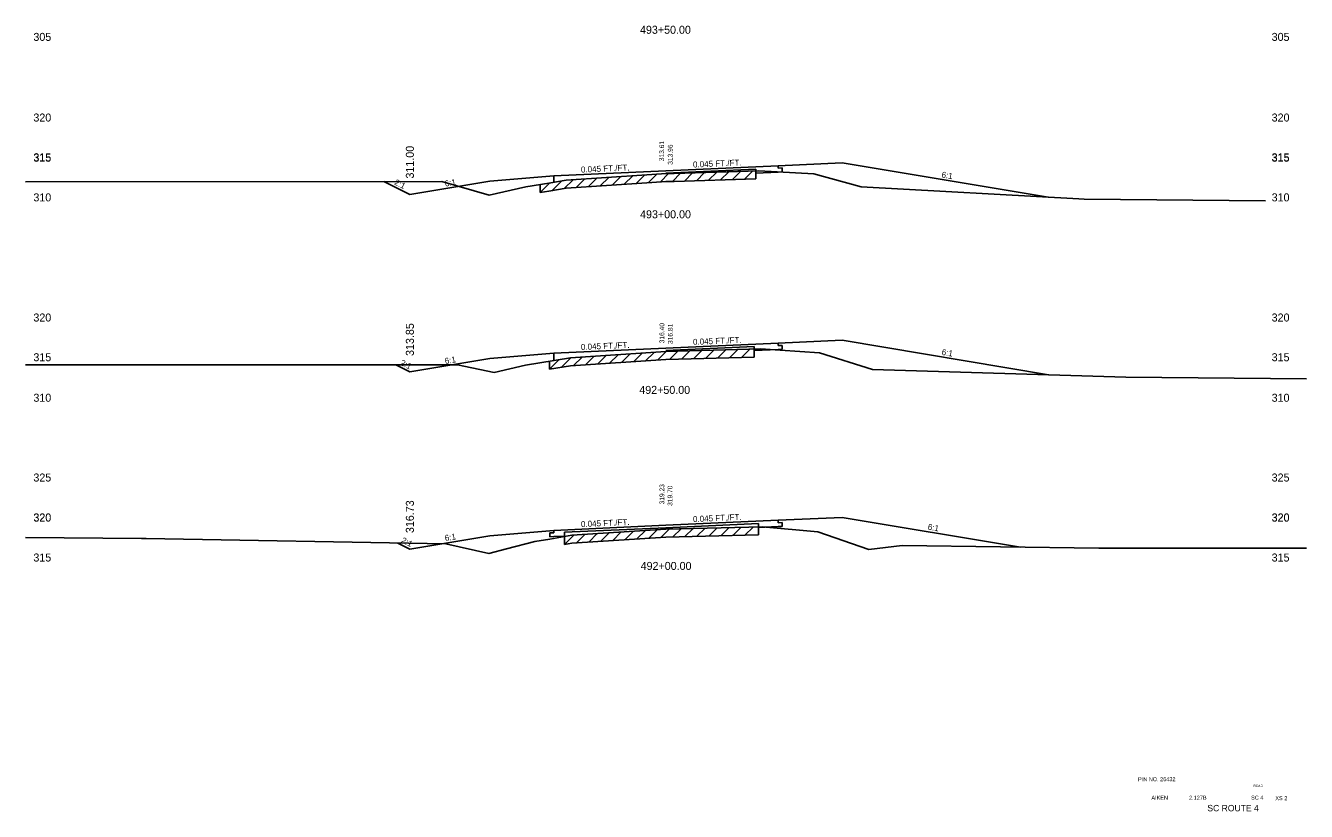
# Model space of a CAD drawing. Extents: x 883 to 1160, y 1002 to 4323.
# Drawn here: x 1000 to 1160, y 1214 to 1312.1 of the extents above; entities that cross this region are included whole.
import ezdxf

# ---------------------------------------------------------------- set-up
doc = ezdxf.new("R2010")
doc.units = 0
for name, color, linetype in [('Level 1', 7, 'Continuous'), ('Level 10', 7, 'Continuous'), ('Level 11', 7, 'Continuous'), ('Level 12', 7, 'Continuous'), ('Level 3', 7, 'Continuous'), ('Level 32', 7, 'Continuous'), ('Level 33', 7, 'Continuous'), ('Level 53', 7, 'Continuous'), ('Level 59', 7, 'Continuous'), ('Level 6', 7, 'Continuous'), ('Level 60', 7, 'Continuous'), ('Level 61', 7, 'Continuous'), ('Level 7', 7, 'Continuous')]:
    doc.layers.add(name, color=color, linetype=linetype)

msp = doc.modelspace()

# ---------------------------------------------------------------- linework, layer by layer
at = {"layer": 'Level 11'}
for p, q in [((1094, 1294.29), (1094, 1294.59)), ((1066, 1292.55), (1066, 1293.33)), ((1094.5, 1294.32), (1094, 1294.29)), ((1094, 1293.81), (1094.5, 1293.84)), ((1094.5, 1293.84), (1094.5, 1294.32)), ((1094, 1272.14), (1094, 1272.44)), ((1094.5, 1272.16), (1094, 1272.14)), ((1094.5, 1271.68), (1094.5, 1272.16)), ((1066, 1270.27), (1066, 1271.18)), ((1094, 1271.66), (1094.5, 1271.68)), ((1094, 1250.03), (1094, 1250.33)), ((1094.5, 1250.05), (1094, 1250.03)), ((1094.5, 1249.57), (1094.5, 1250.05)), ((1066, 1248.77), (1065.5, 1248.75)), ((1065.5, 1248.75), (1065.5, 1248.27)), ((1065.5, 1248.27), (1066, 1248.29)), ((1066, 1249.07), (1066, 1248.77)), ((1094, 1249.55), (1094.5, 1249.57))]:
    msp.add_line(p, q, dxfattribs=at)
at = {"layer": 'Level 12'}
for p, q in [((1091.21, 1293.96), (1091.21, 1293.69)), ((1091.21, 1293.69), (1094, 1293.81)), ((1091, 1271.7), (1091, 1271.53)), ((1091, 1271.53), (1094, 1271.66)), ((1067.34, 1248.35), (1066, 1248.29)), ((1067.34, 1248.32), (1067.34, 1248.35)), ((1091.56, 1249.44), (1094, 1249.55)), ((1091.56, 1249.51), (1091.56, 1249.44))]:
    msp.add_line(p, q, dxfattribs=at)
at = {"layer": 'Level 53'}
for p, q in [((1080, 1293.66), (1091.21, 1294.17)), ((1091.21, 1294.17), (1091.21, 1293.96)), ((1080, 1271.51), (1091, 1272.01)), ((1091, 1272.01), (1091, 1271.7)), ((1080, 1249.4), (1091.56, 1249.92)), ((1091.56, 1249.92), (1091.56, 1249.51)), ((1080, 1249.4), (1067.34, 1248.83)), ((1067.34, 1248.83), (1067.34, 1248.32))]:
    msp.add_line(p, q, dxfattribs=at)
at = {"layer": 'Level 59'}
for p, q in [((1080, 1293.96), (1094, 1294.59)), ((1066, 1293.33), (1080, 1293.96)), ((1080, 1271.81), (1094, 1272.44)), ((1066, 1271.18), (1080, 1271.81)), ((1066, 1249.07), (1080, 1249.7)), ((1080, 1249.7), (1094, 1250.33))]:
    msp.add_line(p, q, dxfattribs=at)
at = {"layer": 'Level 6'}
for p, q in [((1094, 1294.59), (1102, 1294.95)), ((1058, 1292.67), (1066, 1293.33)), ((1094, 1272.44), (1102, 1272.8)), ((1058, 1270.52), (1066, 1271.18)), ((1094, 1250.33), (1102, 1250.69)), ((1058, 1248.4), (1066, 1249.07))]:
    msp.add_line(p, q, dxfattribs=at)
at = {"layer": 'Level 60'}
for p, q in [((1067.54, 1292.8), (1077.61, 1293.47)), ((1077.61, 1293.47), (1079.44, 1293.6)), ((1079.44, 1293.6), (1080, 1293.62)), ((1080, 1293.62), (1081, 1293.65)), ((1081, 1293.65), (1091.58, 1293.98)), ((1091.58, 1293.98), (1098.48, 1293.59)), ((1098.48, 1293.59), (1104.37, 1291.95)), ((1000, 1292.61), (1052, 1292.63)), ((1052, 1292.63), (1057.92, 1290.94)), ((1057.92, 1290.94), (1062.51, 1291.98)), ((1062.51, 1291.98), (1065.37, 1292.44)), ((1065.37, 1292.44), (1067.54, 1292.8)), ((1104.37, 1291.95), (1131.56, 1290.45)), ((1131.56, 1290.45), (1132.26, 1290.43)), ((1132.26, 1290.43), (1154.9, 1290.2)), ((1064.22, 1269.98), (1068.06, 1270.61)), ((1068.06, 1270.61), (1080, 1271.4)), ((1080, 1271.4), (1091.82, 1271.72)), ((1091.82, 1271.72), (1099.16, 1271.23)), ((1099.16, 1271.23), (1105.81, 1269.17)), ((1000, 1269.76), (1050.87, 1269.72)), ((1050.87, 1269.72), (1053.96, 1269.72)), ((1053.96, 1269.72), (1058.54, 1268.8)), ((1058.54, 1268.8), (1062.44, 1269.68)), ((1062.44, 1269.68), (1064.22, 1269.98)), ((1105.81, 1269.17), (1137.43, 1268.22)), ((1137.43, 1268.22), (1160, 1268)), ((1000, 1248.2), (1014.49, 1248.05)), ((1014.49, 1248.05), (1015.07, 1248.05)), ((1015.07, 1248.05), (1052.49, 1247.39)), ((1065.49, 1247.99), (1068.24, 1248.48)), ((1068.24, 1248.48), (1080, 1249.23)), ((1080, 1249.23), (1092.05, 1249.52)), ((1092.05, 1249.52), (1098.96, 1248.9)), ((1098.96, 1248.9), (1105.34, 1246.69)), ((1052.49, 1247.39), (1057.87, 1246.2)), ((1057.87, 1246.2), (1060.09, 1246.76)), ((1060.09, 1246.76), (1063.63, 1247.66)), ((1063.63, 1247.66), (1065.49, 1247.99)), ((1105.34, 1246.69), (1109.5, 1247.17)), ((1109.5, 1247.17), (1134.07, 1246.84)), ((1134.07, 1246.84), (1140.73, 1246.84)), ((1140.73, 1246.84), (1160, 1246.83))]:
    msp.add_line(p, q, dxfattribs=at)
at = {"layer": 'Level 61'}
for p, q in [((1068.39, 1292.85), (1067.29, 1291.76)), ((1069.87, 1292.95), (1068.79, 1291.88)), ((1071.37, 1293.05), (1070.29, 1291.98)), ((1072.87, 1293.15), (1071.79, 1292.08)), ((1074.37, 1293.26), (1073.29, 1292.18)), ((1075.87, 1293.36), (1074.79, 1292.28)), ((1077.37, 1293.46), (1076.29, 1292.39)), ((1078.87, 1293.56), (1077.8, 1292.49)), ((1080.33, 1293.63), (1079.3, 1292.59)), ((1081.83, 1293.67), (1080.8, 1292.64)), ((1081, 1292.65), (1091.21, 1292.96)), ((1083.33, 1293.72), (1082.3, 1292.69)), ((1084.83, 1293.77), (1083.8, 1292.73)), ((1086.33, 1293.81), (1085.3, 1292.78)), ((1087.83, 1293.86), (1086.8, 1292.83)), ((1089.33, 1293.91), (1088.3, 1292.87)), ((1090.83, 1293.95), (1089.8, 1292.92)), ((1091.21, 1292.96), (1091.21, 1293.96)), ((1065.49, 1292.46), (1064.29, 1291.27)), ((1064.29, 1292.27), (1064.29, 1291.27)), ((1064.29, 1291.27), (1065.37, 1291.44)), ((1065.37, 1291.44), (1067.54, 1291.8)), ((1066.99, 1292.71), (1065.79, 1291.51)), ((1067.54, 1291.8), (1077.61, 1292.47)), ((1077.61, 1292.47), (1079.44, 1292.6)), ((1079.44, 1292.6), (1080, 1292.62)), ((1080, 1292.62), (1081, 1292.65)), ((1068.13, 1270.62), (1066.94, 1269.43)), ((1069.51, 1270.71), (1068.44, 1269.64)), ((1071.01, 1270.81), (1069.94, 1269.74)), ((1072.51, 1270.91), (1071.44, 1269.84)), ((1074.01, 1271), (1072.94, 1269.93)), ((1075.51, 1271.1), (1074.44, 1270.03)), ((1077.01, 1271.2), (1075.94, 1270.13)), ((1078.51, 1271.3), (1077.44, 1270.23)), ((1080.01, 1271.4), (1078.94, 1270.33)), ((1080, 1270.4), (1091, 1270.7)), ((1081.47, 1271.44), (1080.44, 1270.41)), ((1082.97, 1271.48), (1081.94, 1270.45)), ((1084.47, 1271.52), (1083.44, 1270.49)), ((1085.97, 1271.56), (1084.94, 1270.53)), ((1087.47, 1271.6), (1086.45, 1270.57)), ((1088.97, 1271.64), (1087.95, 1270.61)), ((1090.48, 1271.68), (1089.45, 1270.65)), ((1091, 1270.7), (1091, 1271.7)), ((1066.63, 1270.38), (1065.44, 1269.18)), ((1065.44, 1270.18), (1065.44, 1269.18)), ((1065.44, 1269.18), (1068.06, 1269.61)), ((1068.06, 1269.61), (1080, 1270.4)), ((1068.52, 1248.5), (1067.34, 1247.32)), ((1067.34, 1248.32), (1067.34, 1247.32)), ((1068.24, 1247.48), (1080, 1248.23)), ((1069.91, 1248.59), (1068.84, 1247.52)), ((1071.41, 1248.68), (1070.34, 1247.61)), ((1072.91, 1248.78), (1071.84, 1247.71)), ((1074.42, 1248.88), (1073.35, 1247.81)), ((1075.92, 1248.97), (1074.85, 1247.9)), ((1077.42, 1249.07), (1076.35, 1248)), ((1078.92, 1249.16), (1077.85, 1248.09)), ((1080.4, 1249.24), (1079.35, 1248.19)), ((1080, 1248.23), (1091.56, 1248.51)), ((1081.88, 1249.28), (1080.85, 1248.25)), ((1083.38, 1249.31), (1082.36, 1248.29)), ((1084.88, 1249.35), (1083.86, 1248.33)), ((1086.38, 1249.39), (1085.36, 1248.36)), ((1087.89, 1249.42), (1086.86, 1248.4)), ((1089.39, 1249.46), (1088.36, 1248.43)), ((1090.89, 1249.49), (1089.86, 1248.47)), ((1091.56, 1248.51), (1091.56, 1249.51)), ((1067.34, 1247.32), (1068.24, 1247.48))]:
    msp.add_line(p, q, dxfattribs=at)
at = {"layer": 'Level 7'}
for p, q in [((1102, 1294.95), (1127.73, 1290.67)), ((1044.74, 1292.63), (1048, 1291)), ((1048, 1291), (1058, 1292.67)), ((1102, 1272.8), (1127.77, 1268.51)), ((1048, 1268.85), (1058, 1270.52)), ((1046.25, 1269.72), (1048, 1268.85)), ((1102, 1250.69), (1124.3, 1246.97)), ((1048, 1246.73), (1058, 1248.4)), ((1046.48, 1247.49), (1048, 1246.73))]:
    msp.add_line(p, q, dxfattribs=at)

# ---------------------------------------------------------------- texts
at = {"layer": 'Level 1'}
for s, height, p in [('493+50.00', 1, (1076.75, 1311.08)), ('493+00.00', 1, (1076.76, 1288.04)), ('492+50.00', 1, (1076.66, 1266.11)), ('492+00.00', 1, (1076.83, 1244.13)), ('PIN NO. 26432', 0.5, (1138.97, 1217.75)), ('AIKEN', 0.5, (1140.64, 1215.44)), (' 2.127B', 0.5, (1145.15, 1215.44)), ('SC ROUTE 4', 0.8, (1147.63, 1213.99)), ('SC 4', 0.5, (1153.09, 1215.44)), ('XS 2', 0.5, (1156.12, 1215.38))]:
    msp.add_text(s, height=height, dxfattribs=at).set_placement(p)
at = {"layer": 'Level 10'}
for s, p in [('313.61', (1079.76, 1295.17)), ('316.40', (1079.79, 1272.43)), ('319.23', (1079.79, 1252.31))]:
    msp.add_text(s, height=0.6, rotation=90, dxfattribs=at).set_placement(p)
at = {"layer": 'Level 3'}
for s, height, p in [(' 305', 1, (1000.6, 1310.19)), (' 305', 1, (1155.29, 1310.19)), (' 320', 1, (1000.6, 1300.12)), (' 320', 1, (1155.29, 1300.12)), (' 315', 1, (1000.6, 1295.16)), (' 315', 1, (1000.6, 1295.1)), (' 315', 1, (1155.29, 1295.16)), (' 315', 1, (1155.29, 1295.1)), (' 310', 1, (1000.6, 1290.15)), (' 310', 1, (1155.29, 1290.15)), (' 320', 1, (1000.6, 1275.15)), (' 320', 1, (1155.29, 1275.15)), (' 315', 1, (1000.6, 1270.19)), (' 315', 1, (1155.29, 1270.19)), (' 310', 1, (1000.6, 1265.13)), (' 310', 1, (1155.29, 1265.13)), (' 325', 1, (1000.6, 1255.17)), (' 325', 1, (1155.29, 1255.17)), (' 320', 1, (1000.6, 1250.19)), (' 320', 1, (1155.29, 1250.19)), (' 320', 1, (1000.6, 1250.16)), (' 320', 1, (1155.29, 1250.16)), (' 315', 1, (1000.6, 1245.18)), (' 315', 1, (1155.29, 1245.18)), ('ROAD', 0.3, (1153.38, 1217.02))]:
    msp.add_text(s, height=height, dxfattribs=at).set_placement(p)
at = {"layer": 'Level 32'}
for s, rotation, p in [('0.045 FT./FT.', 2.5766, (1069.39, 1293.74)), ('0.045 FT./FT.', 2.5766, (1083.39, 1294.37)), ('2:1', 333.435, (1045.98, 1292.29)), ('6:1', 9.4623, (1052.43, 1291.99)), ('6:1', 350.5377, (1114.38, 1293.14)), ('0.045 FT./FT.', 2.5766, (1069.39, 1271.59)), ('0.045 FT./FT.', 2.5766, (1083.39, 1272.22)), ('6:1', 9.4623, (1052.43, 1269.84)), ('6:1', 350.5377, (1114.4, 1270.99)), ('2:1', 333.435, (1046.73, 1269.76)), ('0.045 FT./FT.', 2.5766, (1069.39, 1249.47)), ('0.045 FT./FT.', 2.5766, (1083.39, 1250.1)), ('6:1', 350.5377, (1112.66, 1249.16)), ('2:1', 333.435, (1046.85, 1247.59)), ('6:1', 9.4623, (1052.43, 1247.73))]:
    msp.add_text(s, height=0.75, rotation=rotation, dxfattribs=at).set_placement(p)
at = {"layer": 'Level 33'}
for s, p in [('311.00', (1048.5, 1293)), ('313.85', (1048.5, 1270.85)), ('316.73', (1048.5, 1248.73))]:
    msp.add_text(s, height=1, rotation=90, dxfattribs=at).set_placement(p)
at = {"layer": 'Level 59'}
for s, p in [(' 313.96', (1080.83, 1294.49)), (' 316.81', (1080.84, 1272.11)), (' 319.70', (1080.8, 1251.9))]:
    msp.add_text(s, height=0.6, rotation=90, dxfattribs=at).set_placement(p)

doc.saveas('drawing.dxf')
